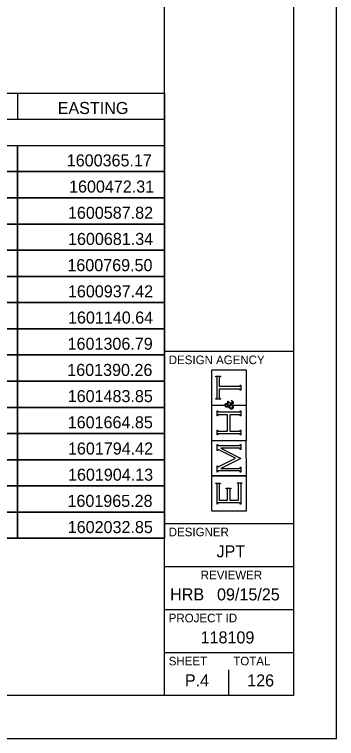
# Model space of a CAD drawing. Extents: x 0 to 34, y 0 to 22.
# Drawn here: x 30.26 to 34, y 0 to 8.41 of the extents above; entities that cross this region are included whole.
import ezdxf

# ---------------------------------------------------------------- set-up
doc = ezdxf.new("R2010")
doc.units = 0
for name, color, linetype in [('SH_Border', 7, 'Continuous'), ('SH_Cut_Line', 7, 'Continuous'), ('SH_Data', 7, 'Continuous'), ('SH_Text', 7, 'Continuous')]:
    doc.layers.add(name, color=color, linetype=linetype)

msp = doc.modelspace()

# ---------------------------------------------------------------- linework, layer by layer
at = {"layer": 'SH_Border'}
for p, q in [((32, 0.5), (32, 21.5)), ((32, 4.5), (33.5, 4.5)), ((32, 2.5), (33.5, 2.5)), ((32, 2), (33.5, 2)), ((32, 1.5), (33.5, 1.5)), ((32, 1), (33.5, 1))]:
    msp.add_line(p, q, dxfattribs=at)
msp.add_lwpolyline([(1.5, 21.5), (33.5, 21.5), (33.5, 0.5), (1.5, 0.5)], close=True, dxfattribs=at)
at = {"layer": 'SH_Cut_Line'}
msp.add_lwpolyline([(0, 0), (34, 0), (34, 22), (0, 22)], close=True, dxfattribs=at)
at = {"layer": 'SH_Data'}
for p, q in [((32.9517, 4.2794), (32.547, 4.2794)), ((32.547, 4.2794), (32.547, 3.8748)), ((32.5978, 4.2041), (32.5978, 4.2106)), ((32.5978, 4.2106), (32.6505, 4.2106)), ((32.6505, 4.2106), (32.6505, 4.2041)), ((32.9517, 3.8748), (32.9517, 4.2794)), ((32.603, 4.2029), (32.5978, 4.2041)), ((32.6064, 4.2011), (32.603, 4.2029)), ((32.6082, 4.1987), (32.6064, 4.2011)), ((32.6099, 4.1964), (32.6082, 4.1987)), ((32.6108, 4.1924), (32.6099, 4.1964)), ((32.6108, 4.1867), (32.6108, 4.1924)), ((32.6108, 3.9675), (32.6108, 4.1867)), ((32.6383, 4.1964), (32.6375, 4.1924)), ((32.6375, 4.1924), (32.6375, 4.1867)), ((32.6375, 4.1867), (32.6375, 4.093)), ((32.64, 4.1987), (32.6383, 4.1964)), ((32.6418, 4.2011), (32.64, 4.1987)), ((32.6452, 4.2029), (32.6418, 4.2011)), ((32.6505, 4.2041), (32.6452, 4.2029)), ((32.6375, 4.093), (32.8639, 4.093)), ((32.8639, 4.0612), (32.6375, 4.0612)), ((32.6375, 4.0612), (32.6375, 3.9676)), ((32.8639, 4.093), (32.8695, 4.093)), ((32.8696, 4.0612), (32.8639, 4.0612)), ((32.8695, 4.093), (32.8734, 4.0939)), ((32.8736, 4.0604), (32.8696, 4.0612)), ((32.8734, 4.0939), (32.8758, 4.0956)), ((32.8759, 4.0586), (32.8736, 4.0604)), ((32.8758, 4.0956), (32.8782, 4.0974)), ((32.8782, 4.0568), (32.8759, 4.0586)), ((32.8782, 4.0974), (32.88, 4.1008)), ((32.88, 4.0534), (32.8782, 4.0568)), ((32.88, 4.1008), (32.8814, 4.106)), ((32.8814, 4.0483), (32.88, 4.0534)), ((32.8814, 4.106), (32.8879, 4.106)), ((32.8879, 4.0483), (32.8814, 4.0483)), ((32.8879, 4.106), (32.8879, 4.0483)), ((32.6064, 3.9531), (32.6082, 3.9555)), ((32.6082, 3.9555), (32.6099, 3.9579)), ((32.6099, 3.9579), (32.6108, 3.9619)), ((32.6108, 3.9619), (32.6108, 3.9675)), ((32.6375, 3.9676), (32.6375, 3.9619)), ((32.6375, 3.9619), (32.6383, 3.9579)), ((32.6383, 3.9579), (32.6401, 3.9555)), ((32.6401, 3.9555), (32.6418, 3.9531)), ((32.547, 3.8748), (32.6961, 3.8748)), ((32.5978, 3.9501), (32.603, 3.9513)), ((32.5978, 3.9436), (32.5978, 3.9501)), ((32.6505, 3.9436), (32.5978, 3.9436)), ((32.603, 3.9513), (32.6064, 3.9531)), ((32.6418, 3.9531), (32.6452, 3.9513)), ((32.6452, 3.9513), (32.6505, 3.9501)), ((32.6505, 3.9501), (32.6505, 3.9436)), ((32.6961, 3.8748), (32.6956, 3.8694)), ((32.7035, 3.8788), (32.7051, 3.8832)), ((32.7035, 3.8734), (32.7035, 3.8788)), ((32.7035, 3.8678), (32.7035, 3.8734)), ((32.7051, 3.8832), (32.7082, 3.8866)), ((32.7082, 3.8866), (32.7114, 3.89)), ((32.7094, 3.8787), (32.7083, 3.8762)), ((32.7083, 3.8762), (32.7083, 3.8732)), ((32.7083, 3.8732), (32.7083, 3.8693)), ((32.7115, 3.8807), (32.7094, 3.8787)), ((32.7114, 3.89), (32.7153, 3.8917)), ((32.7137, 3.8827), (32.7115, 3.8807)), ((32.7164, 3.8837), (32.7137, 3.8827)), ((32.7153, 3.8917), (32.7199, 3.8917)), ((32.7196, 3.8837), (32.7164, 3.8837)), ((32.7238, 3.8837), (32.7196, 3.8837)), ((32.7199, 3.8917), (32.7247, 3.8917)), ((32.7276, 3.8823), (32.7238, 3.8837)), ((32.7247, 3.8917), (32.7289, 3.89)), ((32.731, 3.8795), (32.7276, 3.8823)), ((32.7289, 3.89), (32.7325, 3.8867)), ((32.7344, 3.8767), (32.731, 3.8795)), ((32.7325, 3.8867), (32.7361, 3.8834)), ((32.7374, 3.8725), (32.7344, 3.8767)), ((32.7361, 3.8834), (32.74, 3.8775)), ((32.7401, 3.8668), (32.7374, 3.8725)), ((32.7383, 3.8931), (32.7383, 3.9216)), ((32.7383, 3.9216), (32.7408, 3.9216)), ((32.7408, 3.8931), (32.7383, 3.8931)), ((32.74, 3.8775), (32.7443, 3.8691)), ((32.7408, 3.9216), (32.7411, 3.9177)), ((32.741, 3.895), (32.7408, 3.8931)), ((32.7418, 3.8964), (32.741, 3.895)), ((32.7411, 3.9177), (32.742, 3.9148)), ((32.743, 3.8974), (32.7418, 3.8964)), ((32.742, 3.9148), (32.7434, 3.9129)), ((32.7446, 3.8987), (32.743, 3.8974)), ((32.7434, 3.9129), (32.7448, 3.911)), ((32.7443, 3.8691), (32.7545, 3.8751)), ((32.7464, 3.8994), (32.7446, 3.8987)), ((32.7448, 3.911), (32.7491, 3.9081)), ((32.7485, 3.8994), (32.7464, 3.8994)), ((32.7549, 3.8994), (32.7485, 3.8994)), ((32.7491, 3.9081), (32.7562, 3.9041)), ((32.7545, 3.8751), (32.7638, 3.8812)), ((32.7629, 3.8954), (32.7549, 3.8994)), ((32.7562, 3.9041), (32.7634, 3.9001)), ((32.7723, 3.8874), (32.7629, 3.8954)), ((32.7634, 3.9001), (32.77, 3.8956)), ((32.7638, 3.8812), (32.7723, 3.8874)), ((32.7741, 3.8716), (32.7681, 3.8674)), ((32.77, 3.8956), (32.7762, 3.8905)), ((32.7821, 3.8776), (32.7741, 3.8716)), ((32.7762, 3.8905), (32.7809, 3.8945)), ((32.7788, 3.9232), (32.7806, 3.9258)), ((32.7821, 3.9224), (32.7788, 3.9232)), ((32.7806, 3.9258), (32.787, 3.9241)), ((32.7809, 3.8945), (32.7841, 3.8981)), ((32.7846, 3.9208), (32.7821, 3.9224)), ((32.7859, 3.873), (32.7821, 3.8776)), ((32.7841, 3.8981), (32.786, 3.9013)), ((32.7863, 3.9187), (32.7846, 3.9208)), ((32.7884, 3.8694), (32.7859, 3.873)), ((32.786, 3.9013), (32.7879, 3.9044)), ((32.7909, 3.8856), (32.786, 3.8811)), ((32.786, 3.8811), (32.7911, 3.8755)), ((32.7879, 3.9165), (32.7863, 3.9187)), ((32.787, 3.9241), (32.7917, 3.9214)), ((32.7888, 3.9139), (32.7879, 3.9165)), ((32.7879, 3.9044), (32.7888, 3.9076)), ((32.7888, 3.9108), (32.7888, 3.9139)), ((32.7888, 3.9076), (32.7888, 3.9108)), ((32.7943, 3.8898), (32.7909, 3.8856)), ((32.7911, 3.8755), (32.7946, 3.8705)), ((32.7917, 3.9214), (32.7948, 3.9177)), ((32.7964, 3.8936), (32.7943, 3.8898)), ((32.7946, 3.8705), (32.7965, 3.866)), ((32.7948, 3.9177), (32.7979, 3.914)), ((32.7984, 3.8974), (32.7964, 3.8936)), ((32.7979, 3.914), (32.7994, 3.9097)), ((32.7994, 3.9011), (32.7984, 3.8974)), ((32.8029, 3.8694), (32.799, 3.8748)), ((32.799, 3.8748), (32.9517, 3.8748)), ((32.7994, 3.9097), (32.7994, 3.9048)), ((32.7994, 3.9048), (32.7994, 3.9011)), ((32.6956, 3.8694), (32.5471, 3.8694)), ((32.5471, 3.8694), (32.5471, 3.4648)), ((32.6108, 3.7493), (32.6108, 3.8071)), ((32.6108, 3.8071), (32.6173, 3.8071)), ((32.6173, 3.8071), (32.6186, 3.8019)), ((32.6186, 3.8019), (32.6205, 3.7985)), ((32.6205, 3.7985), (32.6228, 3.7967)), ((32.6228, 3.7967), (32.6251, 3.7949)), ((32.6251, 3.7949), (32.629, 3.7941)), ((32.629, 3.7941), (32.6347, 3.7941)), ((32.6347, 3.7941), (32.8639, 3.7941)), ((32.705, 3.8628), (32.7035, 3.8678)), ((32.7082, 3.8583), (32.705, 3.8628)), ((32.7123, 3.8526), (32.7082, 3.8583)), ((32.7083, 3.8693), (32.7097, 3.8664)), ((32.7097, 3.8664), (32.7125, 3.8644)), ((32.7182, 3.8498), (32.7123, 3.8526)), ((32.7125, 3.8644), (32.7152, 3.8623)), ((32.7152, 3.8623), (32.7179, 3.8614)), ((32.7179, 3.8614), (32.7205, 3.8614)), ((32.7259, 3.8498), (32.7182, 3.8498)), ((32.7205, 3.8614), (32.7227, 3.8614)), ((32.7227, 3.8614), (32.7252, 3.8617)), ((32.7252, 3.8617), (32.7279, 3.8625)), ((32.7286, 3.8498), (32.7259, 3.8498)), ((32.7279, 3.8625), (32.7307, 3.8632)), ((32.7315, 3.8502), (32.7286, 3.8498)), ((32.7307, 3.8632), (32.7347, 3.8647)), ((32.7345, 3.8509), (32.7315, 3.8502)), ((32.7375, 3.8517), (32.7345, 3.8509)), ((32.7347, 3.8647), (32.7401, 3.8668)), ((32.7413, 3.8531), (32.7375, 3.8517)), ((32.746, 3.8552), (32.7413, 3.8531)), ((32.7519, 3.8444), (32.746, 3.8552)), ((32.7561, 3.8603), (32.7505, 3.8575)), ((32.7505, 3.8575), (32.7537, 3.8521)), ((32.7575, 3.837), (32.7519, 3.8444)), ((32.7537, 3.8521), (32.7571, 3.8481)), ((32.7607, 3.8628), (32.7561, 3.8603)), ((32.7571, 3.8481), (32.7609, 3.8454)), ((32.7629, 3.8331), (32.7575, 3.837)), ((32.7644, 3.8651), (32.7607, 3.8628)), ((32.7609, 3.8454), (32.7646, 3.8427)), ((32.7684, 3.8292), (32.7629, 3.8331)), ((32.7681, 3.8674), (32.7644, 3.8651)), ((32.7646, 3.8427), (32.7687, 3.8413)), ((32.7738, 3.8273), (32.7684, 3.8292)), ((32.7687, 3.8413), (32.7731, 3.8413)), ((32.7731, 3.8413), (32.7779, 3.8413)), ((32.7793, 3.8273), (32.7738, 3.8273)), ((32.7779, 3.8413), (32.7822, 3.8429)), ((32.7848, 3.8273), (32.7793, 3.8273)), ((32.7822, 3.8429), (32.7858, 3.846)), ((32.7895, 3.8294), (32.7848, 3.8273)), ((32.7858, 3.846), (32.7895, 3.8491)), ((32.7896, 3.8668), (32.7884, 3.8694)), ((32.7895, 3.8491), (32.7913, 3.8533)), ((32.7935, 3.8338), (32.7895, 3.8294)), ((32.7907, 3.8642), (32.7896, 3.8668)), ((32.7913, 3.8614), (32.7907, 3.8642)), ((32.7913, 3.8586), (32.7913, 3.8614)), ((32.7913, 3.8533), (32.7913, 3.8586)), ((32.7975, 3.8382), (32.7935, 3.8338)), ((32.7965, 3.866), (32.7985, 3.8615)), ((32.7994, 3.8441), (32.7975, 3.8382)), ((32.7985, 3.8615), (32.7994, 3.8567)), ((32.7994, 3.8567), (32.7994, 3.8516)), ((32.7994, 3.8516), (32.7994, 3.8441)), ((32.9517, 3.8694), (32.8029, 3.8694)), ((32.8639, 3.7941), (32.8695, 3.7941)), ((32.8695, 3.7941), (32.8734, 3.7949)), ((32.8734, 3.7949), (32.8758, 3.7967)), ((32.8758, 3.7967), (32.8782, 3.7985)), ((32.8782, 3.7985), (32.88, 3.8019)), ((32.88, 3.8019), (32.8814, 3.8071)), ((32.8814, 3.8071), (32.8879, 3.8071)), ((32.8879, 3.8071), (32.8879, 3.7493)), ((32.9517, 3.4648), (32.9517, 3.8694)), ((32.6173, 3.7493), (32.6108, 3.7493)), ((32.6185, 3.7545), (32.6173, 3.7493)), ((32.6203, 3.7579), (32.6185, 3.7545)), ((32.6227, 3.7597), (32.6203, 3.7579)), ((32.625, 3.7614), (32.6227, 3.7597)), ((32.629, 3.7623), (32.625, 3.7614)), ((32.6347, 3.7623), (32.629, 3.7623)), ((32.732, 3.7623), (32.6347, 3.7623)), ((32.732, 3.5718), (32.732, 3.7623)), ((32.8639, 3.7623), (32.7587, 3.7623)), ((32.7587, 3.7623), (32.7587, 3.5718)), ((32.8696, 3.7623), (32.8639, 3.7623)), ((32.8736, 3.7614), (32.8696, 3.7623)), ((32.8759, 3.7597), (32.8736, 3.7614)), ((32.8782, 3.7579), (32.8759, 3.7597)), ((32.88, 3.7545), (32.8782, 3.7579)), ((32.8814, 3.7493), (32.88, 3.7545)), ((32.8879, 3.7493), (32.8814, 3.7493)), ((32.6108, 3.5271), (32.6108, 3.5848)), ((32.6108, 3.5848), (32.6173, 3.5848)), ((32.6173, 3.5848), (32.6186, 3.5797)), ((32.6203, 3.5357), (32.6185, 3.5322)), ((32.6186, 3.5797), (32.6205, 3.5762)), ((32.6227, 3.5374), (32.6203, 3.5357)), ((32.6205, 3.5762), (32.6228, 3.5745)), ((32.625, 3.5392), (32.6227, 3.5374)), ((32.6228, 3.5745), (32.6251, 3.5727)), ((32.6291, 3.5401), (32.625, 3.5392)), ((32.6251, 3.5727), (32.629, 3.5718)), ((32.629, 3.5718), (32.6347, 3.5718)), ((32.6347, 3.5401), (32.6291, 3.5401)), ((32.6347, 3.5718), (32.732, 3.5718)), ((32.8639, 3.5401), (32.6347, 3.5401)), ((32.7587, 3.5718), (32.8639, 3.5718)), ((32.8639, 3.5718), (32.8696, 3.5718)), ((32.8696, 3.5401), (32.8639, 3.5401)), ((32.8696, 3.5718), (32.8736, 3.5727)), ((32.8736, 3.5392), (32.8696, 3.5401)), ((32.8736, 3.5727), (32.8759, 3.5744)), ((32.8759, 3.5375), (32.8736, 3.5392)), ((32.8759, 3.5744), (32.8782, 3.576)), ((32.8782, 3.5358), (32.8759, 3.5375)), ((32.8782, 3.576), (32.88, 3.5795)), ((32.88, 3.5324), (32.8782, 3.5358)), ((32.88, 3.5795), (32.8814, 3.5848)), ((32.8814, 3.5848), (32.8879, 3.5848)), ((32.8879, 3.5848), (32.8879, 3.5271)), ((32.9516, 3.4593), (32.547, 3.4593)), ((32.547, 3.4593), (32.547, 3.0547)), ((32.5471, 3.4648), (32.9517, 3.4648)), ((32.6173, 3.5271), (32.6108, 3.5271)), ((32.6185, 3.5322), (32.6173, 3.5271)), ((32.75, 3.5), (32.75, 3.5)), ((32.8814, 3.5271), (32.88, 3.5324)), ((32.8879, 3.5271), (32.8814, 3.5271)), ((32.9517, 3.0547), (32.9516, 3.4593)), ((32.6108, 3.3452), (32.6108, 3.4176)), ((32.6108, 3.4176), (32.6173, 3.4176)), ((32.6173, 3.4176), (32.6186, 3.4124)), ((32.6186, 3.4124), (32.6205, 3.409)), ((32.6205, 3.409), (32.6228, 3.4072)), ((32.6228, 3.4072), (32.6251, 3.4055)), ((32.6251, 3.4055), (32.6291, 3.4046)), ((32.6291, 3.4046), (32.6347, 3.4046)), ((32.6347, 3.4046), (32.8639, 3.4046)), ((32.8639, 3.3728), (32.6543, 3.3728)), ((32.6543, 3.3728), (32.8879, 3.2548)), ((32.8639, 3.4046), (32.8695, 3.4046)), ((32.8696, 3.3728), (32.8639, 3.3728)), ((32.8695, 3.4046), (32.8734, 3.4055)), ((32.8736, 3.372), (32.8696, 3.3728)), ((32.8734, 3.4055), (32.8758, 3.4072)), ((32.8759, 3.3703), (32.8736, 3.372)), ((32.8758, 3.4072), (32.8782, 3.409)), ((32.8782, 3.3686), (32.8759, 3.3703)), ((32.8782, 3.409), (32.88, 3.4124)), ((32.88, 3.3651), (32.8782, 3.3686)), ((32.88, 3.4124), (32.8814, 3.4176)), ((32.8814, 3.4176), (32.8879, 3.4176)), ((32.8879, 3.4176), (32.8879, 3.3598)), ((32.6173, 3.3452), (32.6108, 3.3452)), ((32.6196, 3.3518), (32.6173, 3.3452)), ((32.6225, 3.3551), (32.6196, 3.3518)), ((32.626, 3.3551), (32.6225, 3.3551)), ((32.6287, 3.3551), (32.626, 3.3551)), ((32.6333, 3.3535), (32.6287, 3.3551)), ((32.6398, 3.3502), (32.6333, 3.3535)), ((32.8253, 3.2574), (32.6398, 3.3502)), ((32.8814, 3.3598), (32.88, 3.3651)), ((32.8879, 3.3598), (32.8814, 3.3598)), ((32.6414, 3.165), (32.8253, 3.2574)), ((32.8879, 3.2548), (32.6543, 3.1383)), ((32.6108, 3.0965), (32.6108, 3.1682)), ((32.6108, 3.1682), (32.6173, 3.1682)), ((32.6173, 3.1682), (32.6196, 3.1616)), ((32.6196, 3.1616), (32.6224, 3.1583)), ((32.6224, 3.1583), (32.6258, 3.1583)), ((32.6258, 3.1583), (32.6274, 3.1583)), ((32.6274, 3.1583), (32.6326, 3.1605)), ((32.6326, 3.1605), (32.6414, 3.165)), ((32.6543, 3.1383), (32.8639, 3.1383)), ((32.8639, 3.1383), (32.8694, 3.1383)), ((32.8694, 3.1383), (32.8734, 3.1392)), ((32.8734, 3.1392), (32.8758, 3.141)), ((32.8758, 3.141), (32.8782, 3.1427)), ((32.8782, 3.1427), (32.88, 3.1462)), ((32.88, 3.1462), (32.8814, 3.1513)), ((32.8814, 3.1513), (32.8879, 3.1513)), ((32.8879, 3.1513), (32.8879, 3.0965)), ((32.547, 3.0547), (32.9517, 3.0547)), ((32.9517, 3.0493), (32.547, 3.0492)), ((32.547, 3.0492), (32.547, 2.6447)), ((32.6173, 3.0965), (32.6108, 3.0965)), ((32.6185, 3.1016), (32.6173, 3.0965)), ((32.6203, 3.105), (32.6185, 3.1016)), ((32.6227, 3.1068), (32.6203, 3.105)), ((32.625, 3.1086), (32.6227, 3.1068)), ((32.6291, 3.1094), (32.625, 3.1086)), ((32.6347, 3.1094), (32.6291, 3.1094)), ((32.8639, 3.1095), (32.6347, 3.1094)), ((32.8696, 3.1095), (32.8639, 3.1095)), ((32.8736, 3.1086), (32.8696, 3.1095)), ((32.8759, 3.1068), (32.8736, 3.1086)), ((32.8782, 3.1051), (32.8759, 3.1068)), ((32.88, 3.1016), (32.8782, 3.1051)), ((32.8814, 3.0965), (32.88, 3.1016)), ((32.8879, 3.0965), (32.8814, 3.0965)), ((32.9517, 2.6447), (32.9517, 3.0493)), ((32.5978, 2.9624), (32.5978, 2.9689)), ((32.5978, 2.9689), (32.6505, 2.9689)), ((32.603, 2.9611), (32.5978, 2.9624)), ((32.6065, 2.9592), (32.603, 2.9611)), ((32.6082, 2.9569), (32.6065, 2.9592)), ((32.61, 2.9546), (32.6082, 2.9569)), ((32.6108, 2.9506), (32.61, 2.9546)), ((32.6108, 2.9449), (32.6108, 2.9506)), ((32.6108, 2.725), (32.6108, 2.9449)), ((32.6384, 2.9546), (32.6375, 2.9506)), ((32.6375, 2.9506), (32.6375, 2.9449)), ((32.6375, 2.9449), (32.6375, 2.7697)), ((32.6402, 2.957), (32.6384, 2.9546)), ((32.642, 2.9594), (32.6402, 2.957)), ((32.6454, 2.9612), (32.642, 2.9594)), ((32.6505, 2.9624), (32.6454, 2.9612)), ((32.6505, 2.9689), (32.6505, 2.9624)), ((32.8482, 2.9653), (32.8482, 2.9718)), ((32.8482, 2.9718), (32.9009, 2.9718)), ((32.8533, 2.9641), (32.8482, 2.9653)), ((32.8568, 2.9623), (32.8533, 2.9641)), ((32.8586, 2.9599), (32.8568, 2.9623)), ((32.8603, 2.9575), (32.8586, 2.9599)), ((32.8612, 2.9535), (32.8603, 2.9575)), ((32.8612, 2.9478), (32.8612, 2.9535)), ((32.8612, 2.7697), (32.8612, 2.9478)), ((32.8888, 2.9573), (32.8879, 2.9533)), ((32.8879, 2.9533), (32.8879, 2.9476)), ((32.8879, 2.9476), (32.8879, 2.725)), ((32.8905, 2.9597), (32.8888, 2.9573)), ((32.8923, 2.9621), (32.8905, 2.9597)), ((32.8957, 2.9639), (32.8923, 2.9621)), ((32.9009, 2.9653), (32.8957, 2.9639)), ((32.9009, 2.9718), (32.9009, 2.9653)), ((32.719, 2.9018), (32.719, 2.9083)), ((32.719, 2.9083), (32.7717, 2.9083)), ((32.7242, 2.9006), (32.719, 2.9018)), ((32.7276, 2.8988), (32.7242, 2.9006)), ((32.7294, 2.8964), (32.7276, 2.8988)), ((32.7312, 2.894), (32.7294, 2.8964)), ((32.732, 2.89), (32.7312, 2.894)), ((32.732, 2.8844), (32.732, 2.89)), ((32.732, 2.7697), (32.732, 2.8844)), ((32.7596, 2.894), (32.7587, 2.89)), ((32.7587, 2.89), (32.7587, 2.8844)), ((32.7587, 2.8844), (32.7587, 2.7697)), ((32.7614, 2.8964), (32.7596, 2.894)), ((32.7631, 2.8988), (32.7614, 2.8964)), ((32.7666, 2.9006), (32.7631, 2.8988)), ((32.7717, 2.9018), (32.7666, 2.9006)), ((32.7717, 2.9083), (32.7717, 2.9018)), ((32.6173, 2.725), (32.6108, 2.725)), ((32.6187, 2.7301), (32.6173, 2.725)), ((32.6205, 2.7336), (32.6187, 2.7301)), ((32.6228, 2.7354), (32.6205, 2.7336)), ((32.6251, 2.7371), (32.6228, 2.7354)), ((32.6291, 2.738), (32.6251, 2.7371)), ((32.6348, 2.738), (32.6291, 2.738)), ((32.864, 2.738), (32.6348, 2.738)), ((32.6375, 2.7697), (32.732, 2.7697)), ((32.7587, 2.7697), (32.8612, 2.7697)), ((32.8696, 2.738), (32.864, 2.738)), ((32.8736, 2.7372), (32.8696, 2.738)), ((32.8759, 2.7355), (32.8736, 2.7372)), ((32.8782, 2.7338), (32.8759, 2.7355)), ((32.88, 2.7303), (32.8782, 2.7338)), ((32.8814, 2.725), (32.88, 2.7303)), ((32.8879, 2.725), (32.8814, 2.725)), ((32.547, 2.6447), (32.9517, 2.6447)), ((32.75, 0.5), (32.75, 0.8)), ((32.375, 0.675), (32.375, 0.675))]:
    msp.add_line(p, q, dxfattribs=at)
at = {"layer": 'SH_Text'}
for p, q in [((25.1691, 7.5), (32, 7.5)), ((30.2923, 7.5), (30.2923, 7.1957)), ((32, 7.5), (32, 6.8913)), ((25.1691, 7.1957), (32, 7.1957)), ((25.1691, 6.8913), (32, 6.8913)), ((30.2923, 6.8913), (30.2923, 2.3261)), ((32, 6.8913), (32, 2.3261)), ((25.1691, 6.587), (32, 6.587)), ((25.1691, 6.2826), (32, 6.2826)), ((25.1691, 5.9783), (32, 5.9783)), ((25.1691, 5.6739), (32, 5.6739)), ((25.1691, 5.3696), (32, 5.3696)), ((25.1691, 5.0652), (32, 5.0652)), ((25.1691, 4.7609), (32, 4.7609)), ((25.1691, 4.4565), (32, 4.4565)), ((25.1691, 4.1522), (32, 4.1522)), ((25.1691, 3.8478), (32, 3.8478)), ((25.1691, 3.5435), (32, 3.5435)), ((25.1691, 3.2391), (32, 3.2391)), ((25.1691, 2.9348), (32, 2.9348)), ((25.1691, 2.6304), (32, 2.6304)), ((25.1691, 2.3261), (32, 2.3261))]:
    msp.add_line(p, q, dxfattribs=at)
for points in [[(28.5845, 6.8913), (30.2923, 6.8913), (30.2923, 6.587), (28.5845, 6.587)], [(30.2923, 6.8913), (32, 6.8913), (32, 6.587), (30.2923, 6.587)], [(28.5845, 6.587), (30.2923, 6.587), (30.2923, 6.2826), (28.5845, 6.2826)], [(30.2923, 6.587), (32, 6.587), (32, 6.2826), (30.2923, 6.2826)], [(28.5845, 6.2826), (30.2923, 6.2826), (30.2923, 5.9783), (28.5845, 5.9783)], [(30.2923, 6.2826), (32, 6.2826), (32, 5.9783), (30.2923, 5.9783)], [(28.5845, 5.9783), (30.2923, 5.9783), (30.2923, 5.6739), (28.5845, 5.6739)], [(30.2923, 5.9783), (32, 5.9783), (32, 5.6739), (30.2923, 5.6739)], [(28.5845, 5.6739), (30.2923, 5.6739), (30.2923, 5.3696), (28.5845, 5.3696)], [(30.2923, 5.6739), (32, 5.6739), (32, 5.3696), (30.2923, 5.3696)], [(28.5845, 5.3696), (30.2923, 5.3696), (30.2923, 5.0652), (28.5845, 5.0652)], [(30.2923, 5.3696), (32, 5.3696), (32, 5.0652), (30.2923, 5.0652)], [(28.5845, 5.0652), (30.2923, 5.0652), (30.2923, 4.7609), (28.5845, 4.7609)], [(30.2923, 5.0652), (32, 5.0652), (32, 4.7609), (30.2923, 4.7609)], [(28.5845, 4.7609), (30.2923, 4.7609), (30.2923, 4.4565), (28.5845, 4.4565)], [(30.2923, 4.7609), (32, 4.7609), (32, 4.4565), (30.2923, 4.4565)], [(28.5845, 4.4565), (30.2923, 4.4565), (30.2923, 4.1522), (28.5845, 4.1522)], [(30.2923, 4.4565), (32, 4.4565), (32, 4.1522), (30.2923, 4.1522)], [(28.5845, 4.1522), (30.2923, 4.1522), (30.2923, 3.8478), (28.5845, 3.8478)], [(30.2923, 4.1522), (32, 4.1522), (32, 3.8478), (30.2923, 3.8478)], [(28.5845, 3.8478), (30.2923, 3.8478), (30.2923, 3.5435), (28.5845, 3.5435)], [(30.2923, 3.8478), (32, 3.8478), (32, 3.5435), (30.2923, 3.5435)], [(28.5845, 3.5435), (30.2923, 3.5435), (30.2923, 3.2391), (28.5845, 3.2391)], [(30.2923, 3.5435), (32, 3.5435), (32, 3.2391), (30.2923, 3.2391)], [(28.5845, 3.2391), (30.2923, 3.2391), (30.2923, 2.9348), (28.5845, 2.9348)], [(30.2923, 3.2391), (32, 3.2391), (32, 2.9348), (30.2923, 2.9348)], [(28.5845, 2.9348), (30.2923, 2.9348), (30.2923, 2.6304), (28.5845, 2.6304)], [(30.2923, 2.9348), (32, 2.9348), (32, 2.6304), (30.2923, 2.6304)], [(28.5845, 2.6304), (30.2923, 2.6304), (30.2923, 2.3261), (28.5845, 2.3261)], [(30.2923, 2.6304), (32, 2.6304), (32, 2.3261), (30.2923, 2.3261)]]:
    msp.add_lwpolyline(points, close=True, dxfattribs=at)

# ---------------------------------------------------------------- texts
at = {"layer": 'SH_Data'}
for s, height, p in [('DESIGN AGENCY', 0.1, (32.05, 4.35)), ('DESIGNER', 0.1, (32.05, 2.35)), ('JPT', 0.14, (32.6054, 2.105)), ('REVIEWER', 0.1, (32.4218, 1.85)), ('HRB', 0.14, (32.0662, 1.605)), ('09/15/25', 0.14, (32.611, 1.605)), ('PROJECT ID', 0.1, (32.05, 1.35)), ('118109', 0.14, (32.4204, 1.105)), ('SHEET', 0.1, (32.05, 0.85)), ('TOTAL', 0.1, (32.8, 0.85)), ('P.4', 0.14, (32.2374, 0.605)), ('126', 0.14, (32.9617, 0.605))]:
    msp.add_text(s, height=height, dxfattribs=at).set_placement(p)
at = {"layer": 'SH_Text'}
for s, p in [('EASTING', (30.7589, 7.2565)), ('1600365.17', (30.8646, 6.6478)), ('1600472.31', (30.8911, 6.3435)), ('1600587.82', (30.8782, 6.0391)), ('1600681.34', (30.879, 5.7348)), ('1600769.50', (30.8715, 5.4304)), ('1600937.42', (30.8782, 5.1261)), ('1601140.64', (30.879, 4.8217)), ('1601306.79', (30.8743, 4.5174)), ('1601390.26', (30.8703, 4.213)), ('1601483.85', (30.8757, 3.9087)), ('1601664.85', (30.8757, 3.6043)), ('1601794.42', (30.8782, 3.3)), ('1601904.13', (30.879, 2.9957)), ('1601965.28', (30.8727, 2.6913)), ('1602032.85', (30.8757, 2.387))]:
    msp.add_text(s, height=0.14, dxfattribs=at).set_placement(p)

doc.saveas('drawing.dxf')
